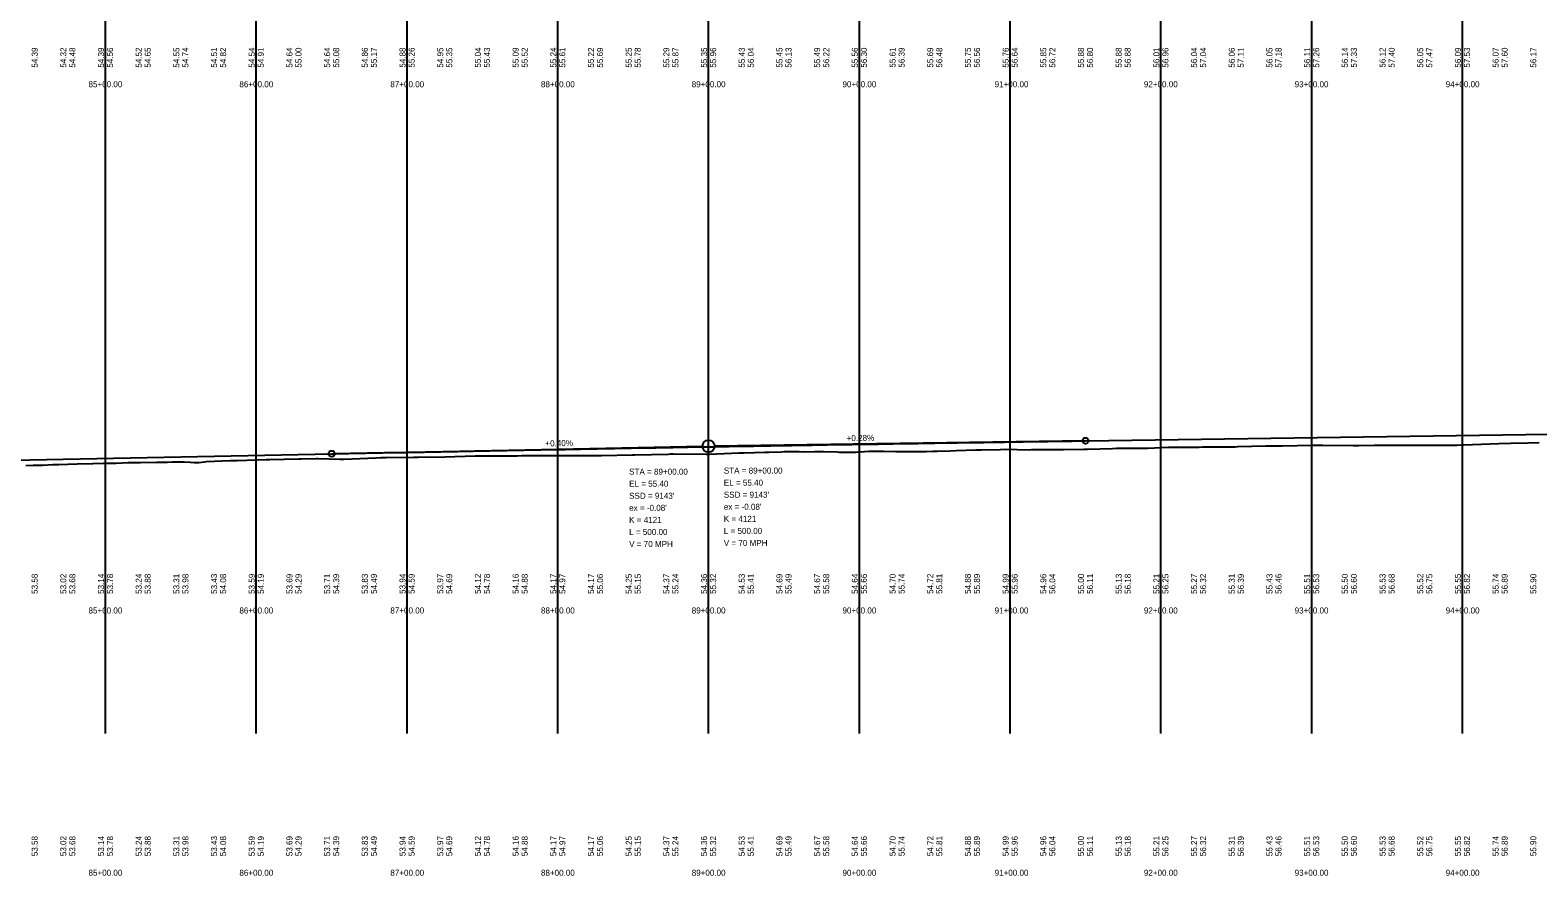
# Model space of a CAD drawing. Extents: x 3880794 to 3915434, y 287517 to 300173.
# Drawn here: x 3907601 to 3908601, y 292382 to 292943 of the extents above; entities that cross this region are included whole.
import ezdxf

# ---------------------------------------------------------------- set-up
doc = ezdxf.new("R2010")
doc.units = 0
for name, color, linetype in [('Level 1', 7, 'Continuous'), ('Level 30', 7, 'Continuous'), ('Level 31', 7, 'Continuous'), ('Level 32', 7, 'Continuous')]:
    doc.layers.add(name, color=color, linetype=linetype)

msp = doc.modelspace()

# ---------------------------------------------------------------- linework, layer by layer
at = {"layer": 'Level 1'}
for p, q in [((3907651.2, 292476.5), (3907651.2, 293504.1)), ((3907751.2, 292476.5), (3907751.2, 293504.1)), ((3907851.2, 292476.5), (3907851.2, 293504.1)), ((3907951.2, 292476.5), (3907951.2, 293504.1)), ((3908051.2, 292476.5), (3908051.2, 293504.1)), ((3908151.2, 292476.5), (3908151.2, 293504.1)), ((3908251.2, 292476.5), (3908251.2, 293504.1)), ((3908351.2, 292476.5), (3908351.2, 293504.1)), ((3908451.2, 292476.5), (3908451.2, 293504.1)), ((3908551.2, 292476.5), (3908551.2, 293504.1)), ((3908301.2, 292670.7), (3909001.2, 292680.6)), ((3908301.2, 292670.7), (3908055.2, 292667.2)), ((3907395.6, 292653.8), (3907801.2, 292662.1)), ((3907801.2, 292662.1), (3908047.2, 292667))]:
    msp.add_line(p, q, dxfattribs=at)
for points in [[(3907666.3, 292656.2), (3907674.4, 292656.3), (3907685.3, 292656.5), (3907691.3, 292656.6), (3907692.2, 292656.6), (3907695.3, 292656.7), (3907703.4, 292656.7), (3907707.4, 292656.6), (3907709.9, 292656.3), (3907713.2, 292656.2), (3907716.8, 292656.7), (3907718.2, 292657), (3907733.8, 292657.5), (3907734.8, 292657.5), (3907736.7, 292657.6), (3907737.5, 292657.6), (3907738.5, 292657.6), (3907757.8, 292658.3), (3907758.9, 292658.3), (3907759.9, 292658.3), (3907779.5, 292658.6), (3907780.9, 292658.6), (3907791, 292659), (3907792.2, 292658.9), (3907806.6, 292658.5), (3907809.3, 292658.5), (3907830.4, 292659.4), (3907833.8, 292659.6), (3907837.3, 292659.6), (3907855.6, 292659.8), (3907858.5, 292659.9), (3907876.2, 292660), (3907896.3, 292660.7), (3907899.7, 292660.7), (3907902.4, 292660.7), (3907924, 292660.8), (3907924.4, 292660.8), (3907927.3, 292660.9), (3907938.7, 292661), (3907941.4, 292661), (3907961.3, 292661), (3907964.2, 292661), (3907977.2, 292660.9), (3907980.1, 292660.9), (3908000.7, 292661.3), (3908002.2, 292661.4), (3908024.5, 292661.9), (3908025.9, 292662), (3908027.1, 292662), (3908027.7, 292662), (3908049.5, 292661.9), (3908050.2, 292661.9), (3908050.9, 292661.9), (3908051.9, 292661.9), (3908071.3, 292662.7), (3908072.4, 292662.7), (3908073.6, 292662.7), (3908074.9, 292662.7), (3908088.5, 292663.1), (3908089.7, 292663.1), (3908091.2, 292663.2), (3908099.6, 292663.4), (3908101.4, 292663.6), (3908103.8, 292663.6), (3908111.2, 292663.5), (3908114.7, 292663.3), (3908121.5, 292663.5), (3908127.5, 292663.5), (3908136.4, 292663.3), (3908137.8, 292663.2), (3908138.7, 292663.2), (3908144.4, 292663.2), (3908148.1, 292663.2), (3908148.6, 292663.2), (3908157.5, 292663.7), (3908165.6, 292663.8), (3908167.3, 292663.8), (3908175.4, 292663.6), (3908176.4, 292663.6), (3908177.9, 292663.6), (3908193.6, 292663.5), (3908195.4, 292663.5), (3908200, 292663.7), (3908201.3, 292663.7), (3908203, 292663.7), (3908211.4, 292664.1), (3908215.3, 292664.2), (3908228.4, 292664.6), (3908232.2, 292664.7), (3908244.5, 292665), (3908248.1, 292665.2), (3908263.8, 292664.7), (3908265.4, 292664.8), (3908267.9, 292664.8), (3908283.5, 292665), (3908286.7, 292665), (3908300, 292665.1), (3908302.6, 292665.1), (3908319.1, 292665.6), (3908321.7, 292665.7), (3908324.2, 292665.7)], [(3908324.2, 292665.7), (3908340, 292665.7), (3908342.2, 292665.7), (3908356.2, 292666.4), (3908359.3, 292666.4), (3908376.6, 292666.5), (3908378.8, 292666.6), (3908382.5, 292666.7), (3908400.4, 292666.6), (3908402.3, 292666.8), (3908420.8, 292667.3), (3908423.9, 292667.3), (3908426.5, 292667.3), (3908428.8, 292667.3), (3908431.7, 292667.3), (3908451.7, 292667.7), (3908455, 292667.7), (3908458.7, 292667.7), (3908478.8, 292667.6), (3908482.2, 292667.6), (3908492.6, 292667.7), (3908498, 292667.7), (3908509.8, 292667.8), (3908510.7, 292667.8), (3908523.2, 292667.7), (3908528.9, 292667.7), (3908542.7, 292667.7), (3908547.4, 292667.7), (3908551.9, 292667.9), (3908563.8, 292668.4), (3908575.4, 292668.8), (3908583, 292669), (3908594.6, 292669.4), (3908602, 292669.6)], [(3907598.4, 292654.3), (3907603.2, 292654.4), (3907609.3, 292654.5), (3907616.2, 292654.9), (3907620.3, 292655), (3907626.3, 292655.2), (3907632.4, 292655.3), (3907642.7, 292655.5), (3907649.9, 292655.8), (3907658.3, 292655.9), (3907666.3, 292656.2)]]:
    msp.add_lwpolyline(points, dxfattribs=at)
msp.add_circle((3908051.2, 292667.1), 4, dxfattribs=at)
msp.add_spline([(3907801.2, 292662.1), (3907811.2, 292662.3), (3907821.2, 292662.5), (3907831.2, 292662.7), (3907841.2, 292662.9), (3907851.2, 292663), (3907861.2, 292663.2), (3907871.2, 292663.4), (3907881.2, 292663.6), (3907891.2, 292663.8), (3907901.2, 292664), (3907911.2, 292664.2), (3907921.2, 292664.4), (3907931.2, 292664.6), (3907941.2, 292664.8), (3907951.2, 292664.9), (3907961.2, 292665.1), (3907971.2, 292665.3), (3907981.2, 292665.5), (3907991.2, 292665.7), (3908001.2, 292665.9), (3908011.2, 292666), (3908021.2, 292666.2), (3908031.2, 292666.4), (3908041.2, 292666.6), (3908051.2, 292666.7), (3908061.2, 292666.9), (3908071.2, 292667.1), (3908081.2, 292667.2), (3908091.2, 292667.4), (3908101.2, 292667.6), (3908111.2, 292667.7), (3908121.2, 292667.9), (3908131.2, 292668.1), (3908141.2, 292668.2), (3908151.2, 292668.4), (3908161.2, 292668.5), (3908171.2, 292668.7), (3908181.2, 292668.9), (3908191.2, 292669), (3908201.2, 292669.2), (3908211.2, 292669.3), (3908221.2, 292669.5), (3908231.2, 292669.6), (3908241.2, 292669.8), (3908251.2, 292669.9), (3908261.2, 292670.1), (3908271.2, 292670.2), (3908281.2, 292670.4), (3908291.2, 292670.5), (3908301.2, 292670.7)], degree=3, dxfattribs=at)
at = {"layer": 'Level 31'}
for centre in [(3908301.2, 292670.7), (3907801.2, 292662.1)]:
    msp.add_circle(centre, 2, dxfattribs=at)

# ---------------------------------------------------------------- texts
at = {"layer": 'Level 30'}
for s, p in [('85+00.00', (3907639.9, 292905.2)), ('85+00.00', (3907639.9, 292905.2)), ('86+00.00', (3907740, 292905.2)), ('86+00.00', (3907740, 292905.2)), ('87+00.00', (3907840.1, 292905.2)), ('87+00.00', (3907840.1, 292905.2)), ('88+00.00', (3907940, 292905.2)), ('88+00.00', (3907940, 292905.2)), ('89+00.00', (3908040, 292905.2)), ('89+00.00', (3908040, 292905.2)), ('90+00.00', (3908140, 292905.2)), ('90+00.00', (3908140, 292905.2)), ('91+00.00', (3908240.9, 292905.2)), ('91+00.00', (3908240.9, 292905.2)), ('92+00.00', (3908339.9, 292905.2)), ('92+00.00', (3908339.9, 292905.2)), ('93+00.00', (3908439.9, 292905.2)), ('93+00.00', (3908439.9, 292905.2)), ('94+00.00', (3908540.1, 292905.2)), ('94+00.00', (3908540.1, 292905.2)), ('85+00.00', (3907639.9, 292556.1)), ('85+00.00', (3907639.9, 292556.1)), ('86+00.00', (3907740, 292556.1)), ('86+00.00', (3907740, 292556.1)), ('87+00.00', (3907840.1, 292556.1)), ('87+00.00', (3907840.1, 292556.1)), ('88+00.00', (3907940, 292556.1)), ('88+00.00', (3907940, 292556.1)), ('89+00.00', (3908040, 292556.1)), ('89+00.00', (3908040, 292556.1)), ('90+00.00', (3908140, 292556.1)), ('90+00.00', (3908140, 292556.1)), ('91+00.00', (3908240.9, 292556.1)), ('91+00.00', (3908240.9, 292556.1)), ('92+00.00', (3908339.9, 292556.1)), ('92+00.00', (3908339.9, 292556.1)), ('93+00.00', (3908439.9, 292556.1)), ('93+00.00', (3908439.9, 292556.1)), ('94+00.00', (3908540.1, 292556.1)), ('94+00.00', (3908540.1, 292556.1)), ('85+00.00', (3907639.9, 292382.1)), ('85+00.00', (3907639.9, 292382.1)), ('86+00.00', (3907740, 292382.1)), ('86+00.00', (3907740, 292382.1)), ('87+00.00', (3907840.1, 292382.1)), ('87+00.00', (3907840.1, 292382.1)), ('88+00.00', (3907940, 292382.1)), ('88+00.00', (3907940, 292382.1)), ('89+00.00', (3908040, 292382.1)), ('89+00.00', (3908040, 292382.1)), ('90+00.00', (3908140, 292382.1)), ('90+00.00', (3908140, 292382.1)), ('91+00.00', (3908240.9, 292382.1)), ('91+00.00', (3908240.9, 292382.1)), ('92+00.00', (3908339.9, 292382.1)), ('92+00.00', (3908339.9, 292382.1)), ('93+00.00', (3908439.9, 292382.1)), ('93+00.00', (3908439.9, 292382.1)), ('94+00.00', (3908540.1, 292382.1)), ('94+00.00', (3908540.1, 292382.1))]:
    msp.add_text(s, height=4, dxfattribs=at).set_placement(p)
at = {"layer": 'Level 31'}
for s, rotation, p in [('+0.40%', 1.1591, (3907943, 292666.9)), ('+0.28%', 0.8116, (3908142.8, 292670.4)), ('53.58', 90, (3907606.2, 292569.1)), ('53.02', 90, (3907625.2, 292569.1)), ('53.68', 90, (3907631.2, 292569.1)), ('53.14', 90, (3907650.2, 292569.1)), ('53.78', 90, (3907656.2, 292569.1)), ('53.24', 90, (3907675.2, 292569.1)), ('53.88', 90, (3907681.2, 292569.1)), ('53.31', 90, (3907700.2, 292569.1)), ('53.98', 90, (3907706.2, 292569.1)), ('53.43', 90, (3907725.2, 292569.1)), ('54.08', 90, (3907731.2, 292569.1)), ('53.59', 90, (3907750.2, 292569.1)), ('54.19', 90, (3907756.2, 292569.1)), ('53.69', 90, (3907775.2, 292569.1)), ('54.29', 90, (3907781.2, 292569.1)), ('53.71', 90, (3907800.2, 292569.1)), ('54.39', 90, (3907806.2, 292569.1)), ('53.83', 90, (3907825.2, 292569.1)), ('54.49', 90, (3907831.2, 292569.1)), ('53.94', 90, (3907850.2, 292569.1)), ('54.59', 90, (3907856.2, 292569.1)), ('53.97', 90, (3907875.2, 292569.1)), ('54.69', 90, (3907881.2, 292569.1)), ('54.12', 90, (3907900.2, 292569.1)), ('54.78', 90, (3907906.2, 292569.1)), ('54.16', 90, (3907925.2, 292569.1)), ('54.88', 90, (3907931.2, 292569.1)), ('54.17', 90, (3907950.2, 292569.1)), ('54.97', 90, (3907956.2, 292569.1)), ('54.17', 90, (3907975.2, 292569.1)), ('55.06', 90, (3907981.2, 292569.1)), ('54.25', 90, (3908000.2, 292569.1)), ('55.15', 90, (3908006.2, 292569.1)), ('54.37', 90, (3908025.2, 292569.1)), ('55.24', 90, (3908031.2, 292569.1)), ('54.36', 90, (3908050.2, 292569.1)), ('55.32', 90, (3908056.2, 292569.1)), ('54.53', 90, (3908075.2, 292569.1)), ('55.41', 90, (3908081.2, 292569.1)), ('54.69', 90, (3908100.2, 292569.1)), ('55.49', 90, (3908106.2, 292569.1)), ('54.67', 90, (3908125.2, 292569.1)), ('55.58', 90, (3908131.2, 292569.1)), ('54.64', 90, (3908150.2, 292569.1)), ('55.66', 90, (3908156.2, 292569.1)), ('54.70', 90, (3908175.2, 292569.1)), ('55.74', 90, (3908181.2, 292569.1)), ('54.72', 90, (3908200.2, 292569.1)), ('55.81', 90, (3908206.2, 292569.1)), ('54.88', 90, (3908225.2, 292569.1)), ('55.89', 90, (3908231.2, 292569.1)), ('54.99', 90, (3908250.2, 292569.1)), ('55.96', 90, (3908256.2, 292569.1)), ('54.96', 90, (3908275.2, 292569.1)), ('56.04', 90, (3908281.2, 292569.1)), ('55.00', 90, (3908300.2, 292569.1)), ('56.11', 90, (3908306.2, 292569.1)), ('55.13', 90, (3908325.2, 292569.1)), ('56.18', 90, (3908331.2, 292569.1)), ('55.21', 90, (3908350.2, 292569.1)), ('56.25', 90, (3908356.2, 292569.1)), ('55.27', 90, (3908375.2, 292569.1)), ('56.32', 90, (3908381.2, 292569.1)), ('55.31', 90, (3908400.2, 292569.1)), ('56.39', 90, (3908406.2, 292569.1)), ('55.43', 90, (3908425.2, 292569.1)), ('56.46', 90, (3908431.2, 292569.1)), ('55.51', 90, (3908450.2, 292569.1)), ('56.53', 90, (3908456.2, 292569.1)), ('55.50', 90, (3908475.2, 292569.1)), ('56.60', 90, (3908481.2, 292569.1)), ('55.53', 90, (3908500.2, 292569.1)), ('56.68', 90, (3908506.2, 292569.1)), ('55.52', 90, (3908525.2, 292569.1)), ('56.75', 90, (3908531.2, 292569.1)), ('55.55', 90, (3908550.2, 292569.1)), ('56.82', 90, (3908556.2, 292569.1)), ('55.74', 90, (3908575.2, 292569.1)), ('56.89', 90, (3908581.2, 292569.1)), ('55.90', 90, (3908600.2, 292569.1)), ('53.58', 90, (3907606.2, 292395.1)), ('53.02', 90, (3907625.2, 292395.1)), ('53.68', 90, (3907631.2, 292395.1)), ('53.14', 90, (3907650.2, 292395.1)), ('53.78', 90, (3907656.2, 292395.1)), ('53.24', 90, (3907675.2, 292395.1)), ('53.88', 90, (3907681.2, 292395.1)), ('53.31', 90, (3907700.2, 292395.1)), ('53.98', 90, (3907706.2, 292395.1)), ('53.43', 90, (3907725.2, 292395.1)), ('54.08', 90, (3907731.2, 292395.1)), ('53.59', 90, (3907750.2, 292395.1)), ('54.19', 90, (3907756.2, 292395.1)), ('53.69', 90, (3907775.2, 292395.1)), ('54.29', 90, (3907781.2, 292395.1)), ('53.71', 90, (3907800.2, 292395.1)), ('54.39', 90, (3907806.2, 292395.1)), ('53.83', 90, (3907825.2, 292395.1)), ('54.49', 90, (3907831.2, 292395.1)), ('53.94', 90, (3907850.2, 292395.1)), ('54.59', 90, (3907856.2, 292395.1)), ('53.97', 90, (3907875.2, 292395.1)), ('54.69', 90, (3907881.2, 292395.1)), ('54.12', 90, (3907900.2, 292395.1)), ('54.78', 90, (3907906.2, 292395.1)), ('54.16', 90, (3907925.2, 292395.1)), ('54.88', 90, (3907931.2, 292395.1)), ('54.17', 90, (3907950.2, 292395.1)), ('54.97', 90, (3907956.2, 292395.1)), ('54.17', 90, (3907975.2, 292395.1)), ('55.06', 90, (3907981.2, 292395.1)), ('54.25', 90, (3908000.2, 292395.1)), ('55.15', 90, (3908006.2, 292395.1)), ('54.37', 90, (3908025.2, 292395.1)), ('55.24', 90, (3908031.2, 292395.1)), ('54.36', 90, (3908050.2, 292395.1)), ('55.32', 90, (3908056.2, 292395.1)), ('54.53', 90, (3908075.2, 292395.1)), ('55.41', 90, (3908081.2, 292395.1)), ('54.69', 90, (3908100.2, 292395.1)), ('55.49', 90, (3908106.2, 292395.1)), ('54.67', 90, (3908125.2, 292395.1)), ('55.58', 90, (3908131.2, 292395.1)), ('54.64', 90, (3908150.2, 292395.1)), ('55.66', 90, (3908156.2, 292395.1)), ('54.70', 90, (3908175.2, 292395.1)), ('55.74', 90, (3908181.2, 292395.1)), ('54.72', 90, (3908200.2, 292395.1)), ('55.81', 90, (3908206.2, 292395.1)), ('54.88', 90, (3908225.2, 292395.1)), ('55.89', 90, (3908231.2, 292395.1)), ('54.99', 90, (3908250.2, 292395.1)), ('55.96', 90, (3908256.2, 292395.1)), ('54.96', 90, (3908275.2, 292395.1)), ('56.04', 90, (3908281.2, 292395.1)), ('55.00', 90, (3908300.2, 292395.1)), ('56.11', 90, (3908306.2, 292395.1)), ('55.13', 90, (3908325.2, 292395.1)), ('56.18', 90, (3908331.2, 292395.1)), ('55.21', 90, (3908350.2, 292395.1)), ('56.25', 90, (3908356.2, 292395.1)), ('55.27', 90, (3908375.2, 292395.1)), ('56.32', 90, (3908381.2, 292395.1)), ('55.31', 90, (3908400.2, 292395.1)), ('56.39', 90, (3908406.2, 292395.1)), ('55.43', 90, (3908425.2, 292395.1)), ('56.46', 90, (3908431.2, 292395.1)), ('55.51', 90, (3908450.2, 292395.1)), ('56.53', 90, (3908456.2, 292395.1)), ('55.50', 90, (3908475.2, 292395.1)), ('56.60', 90, (3908481.2, 292395.1)), ('55.53', 90, (3908500.2, 292395.1)), ('56.68', 90, (3908506.2, 292395.1)), ('55.52', 90, (3908525.2, 292395.1)), ('56.75', 90, (3908531.2, 292395.1)), ('55.55', 90, (3908550.2, 292395.1)), ('56.82', 90, (3908556.2, 292395.1)), ('55.74', 90, (3908575.2, 292395.1)), ('56.89', 90, (3908581.2, 292395.1)), ('55.90', 90, (3908600.2, 292395.1))]:
    msp.add_text(s, height=4, rotation=rotation, dxfattribs=at).set_placement(p)
for s, p in [('STA = 89+00.00', (3907998.5, 292648.2)), ('STA = 89+00.00', (3908061.3, 292648.9)), ('EL = 55.40', (3907998.5, 292640.2)), ('EL = 55.40', (3908061.3, 292640.9)), ("SSD = 9143'", (3907998.5, 292632.2)), ("SSD = 9143'", (3908061.3, 292632.9)), ("ex = -0.08'", (3907998.5, 292624.2)), ('K = 4121', (3907998.5, 292616.2)), ("ex = -0.08'", (3908061.3, 292624.9)), ('K = 4121', (3908061.3, 292616.9)), ('L = 500.00', (3907998.5, 292608.2)), ('L = 500.00', (3908061.3, 292608.9)), ('V = 70 MPH', (3907998.5, 292600.2)), ('V = 70 MPH', (3908061.3, 292600.9))]:
    msp.add_text(s, height=4, dxfattribs=at).set_placement(p)
at = {"layer": 'Level 32'}
for s, p in [('54.39', (3907606.2, 292918.2)), ('54.32', (3907625.2, 292918.2)), ('54.48', (3907631.2, 292918.2)), ('54.39', (3907650.2, 292918.2)), ('54.56', (3907656.2, 292918.2)), ('54.52', (3907675.2, 292918.2)), ('54.65', (3907681.2, 292918.2)), ('54.55', (3907700.2, 292918.2)), ('54.74', (3907706.2, 292918.2)), ('54.51', (3907725.2, 292918.2)), ('54.82', (3907731.2, 292918.2)), ('54.54', (3907750.2, 292918.2)), ('54.91', (3907756.2, 292918.2)), ('54.64', (3907775.2, 292918.2)), ('55.00', (3907781.2, 292918.2)), ('54.64', (3907800.2, 292918.2)), ('55.08', (3907806.2, 292918.2)), ('54.86', (3907825.2, 292918.2)), ('55.17', (3907831.2, 292918.2)), ('54.88', (3907850.2, 292918.2)), ('55.26', (3907856.2, 292918.2)), ('54.95', (3907875.2, 292918.2)), ('55.35', (3907881.2, 292918.2)), ('55.04', (3907900.2, 292918.2)), ('55.43', (3907906.2, 292918.2)), ('55.09', (3907925.2, 292918.2)), ('55.52', (3907931.2, 292918.2)), ('55.24', (3907950.2, 292918.2)), ('55.61', (3907956.2, 292918.2)), ('55.22', (3907975.2, 292918.2)), ('55.69', (3907981.2, 292918.2)), ('55.25', (3908000.2, 292918.2)), ('55.78', (3908006.2, 292918.2)), ('55.29', (3908025.2, 292918.2)), ('55.87', (3908031.2, 292918.2)), ('55.35', (3908050.2, 292918.2)), ('55.96', (3908056.2, 292918.2)), ('55.43', (3908075.2, 292918.2)), ('56.04', (3908081.2, 292918.2)), ('55.45', (3908100.2, 292918.2)), ('56.13', (3908106.2, 292918.2)), ('55.49', (3908125.2, 292918.2)), ('56.22', (3908131.2, 292918.2)), ('55.56', (3908150.2, 292918.2)), ('56.30', (3908156.2, 292918.2)), ('55.61', (3908175.2, 292918.2)), ('56.39', (3908181.2, 292918.2)), ('55.69', (3908200.2, 292918.2)), ('56.48', (3908206.2, 292918.2)), ('55.75', (3908225.2, 292918.2)), ('56.56', (3908231.2, 292918.2)), ('55.76', (3908250.2, 292918.2)), ('56.64', (3908256.2, 292918.2)), ('55.85', (3908275.2, 292918.2)), ('56.72', (3908281.2, 292918.2)), ('55.88', (3908300.2, 292918.2)), ('56.80', (3908306.2, 292918.2)), ('55.88', (3908325.2, 292918.2)), ('56.88', (3908331.2, 292918.2)), ('56.01', (3908350.2, 292918.2)), ('56.96', (3908356.2, 292918.2)), ('56.04', (3908375.2, 292918.2)), ('57.04', (3908381.2, 292918.2)), ('56.06', (3908400.2, 292918.2)), ('57.11', (3908406.2, 292918.2)), ('56.05', (3908425.2, 292918.2)), ('57.18', (3908431.2, 292918.2)), ('56.11', (3908450.2, 292918.2)), ('57.26', (3908456.2, 292918.2)), ('56.14', (3908475.2, 292918.2)), ('57.33', (3908481.2, 292918.2)), ('56.12', (3908500.2, 292918.2)), ('57.40', (3908506.2, 292918.2)), ('56.05', (3908525.2, 292918.2)), ('57.47', (3908531.2, 292918.2)), ('56.09', (3908550.2, 292918.2)), ('57.53', (3908556.2, 292918.2)), ('56.07', (3908575.2, 292918.2)), ('57.60', (3908581.2, 292918.2)), ('56.17', (3908600.2, 292918.2))]:
    msp.add_text(s, height=4, rotation=90, dxfattribs=at).set_placement(p)

doc.saveas('drawing.dxf')
